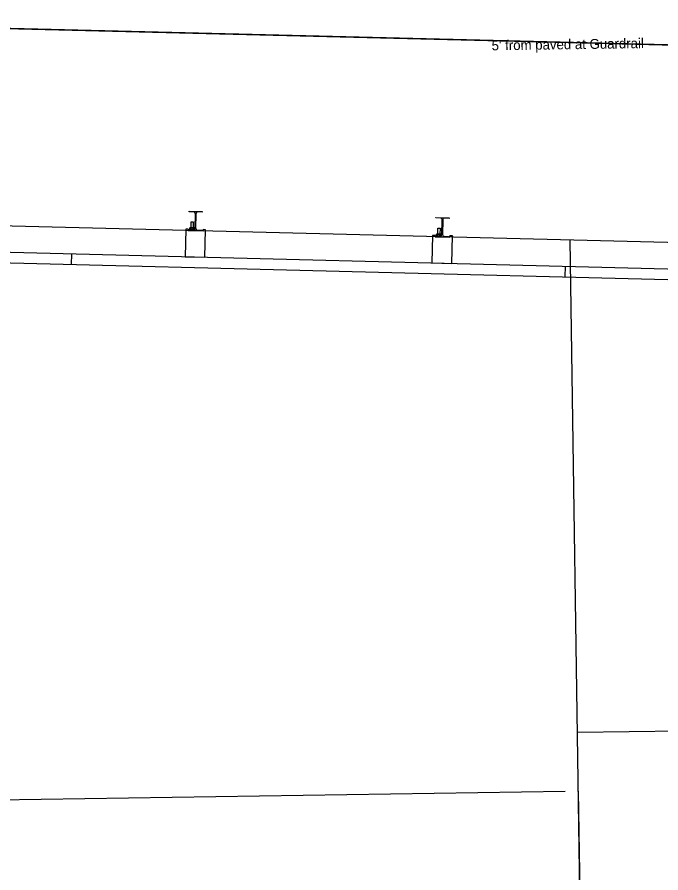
# Model space of a CAD drawing. Extents: x 17498307 to 17498862, y 7167523 to 7167641.
# Drawn here: x 17498396.78 to 17498413.08, y 7167588.49 to 7167610.15 of the extents above; entities that cross this region are included whole.
import ezdxf

# ---------------------------------------------------------------- set-up
doc = ezdxf.new("R2010")
doc.units = 0
for name, color, linetype in [('_CIVIL_CONSTRUCTION', 7, 'Continuous'), ('Draft_DNC', 7, 'Continuous'), ('dsnCellsHighwaySymbols', 7, 'Continuous'), ('Sawcut', 7, 'Continuous'), ('TextAlignmentSml', 7, 'Continuous'), ('TL_ForeSlopeBarnRoof', 7, 'Continuous')]:
    doc.layers.add(name, color=color, linetype=linetype)

msp = doc.modelspace()

# ---------------------------------------------------------------- linework, layer by layer
at = {"layer": '_CIVIL_CONSTRUCTION'}
for p, q in [((17498411.495, 7167556.438), (17498410.778, 7167604.508)), ((17498410.964, 7167592.047), (17498460.958, 7167592.793))]:
    msp.add_line(p, q, dxfattribs=at)
msp.add_lwpolyline([(17498432.532, 7167603.967), (17498384.798, 7167605.153)], dxfattribs=at)
at = {"layer": 'Draft_DNC'}
msp.add_line((17498432.656, 7167608.966), (17498384.922, 7167610.151), dxfattribs=at)
at = {"layer": 'dsnCellsHighwaySymbols'}
for p, q in [((17498401.134, 7167605.223), (17498401.134, 7167605.239)), ((17498401.134, 7167605.239), (17498401.467, 7167605.23)), ((17498401.134, 7167605.223), (17498401.134, 7167605.239)), ((17498401.134, 7167605.239), (17498401.467, 7167605.23)), ((17498401.251, 7167605.22), (17498401.134, 7167605.223)), ((17498401.251, 7167605.22), (17498401.134, 7167605.223)), ((17498401.282, 7167604.803), (17498401.292, 7167605.178)), ((17498401.282, 7167604.803), (17498401.292, 7167605.178)), ((17498401.307, 7167605.177), (17498401.298, 7167604.802)), ((17498401.307, 7167605.177), (17498401.298, 7167604.802)), ((17498401.467, 7167605.215), (17498401.35, 7167605.218)), ((17498401.467, 7167605.215), (17498401.35, 7167605.218)), ((17498401.467, 7167605.23), (17498401.467, 7167605.215)), ((17498401.467, 7167605.23), (17498401.467, 7167605.215)), ((17498401.181, 7167604.816), (17498401.185, 7167604.967)), ((17498401.185, 7167604.967), (17498401.237, 7167604.965)), ((17498401.237, 7167604.965), (17498401.233, 7167604.814)), ((17498407.382, 7167605.081), (17498407.715, 7167605.073)), ((17498407.382, 7167605.066), (17498407.382, 7167605.081)), ((17498407.499, 7167605.063), (17498407.382, 7167605.066)), ((17498407.53, 7167604.645), (17498407.54, 7167605.02)), ((17498407.555, 7167605.02), (17498407.546, 7167604.645)), ((17498407.715, 7167605.057), (17498407.598, 7167605.06)), ((17498407.715, 7167605.073), (17498407.715, 7167605.057)), ((17498401.05, 7167604.782), (17498401.032, 7167604.086)), ((17498401.112, 7167604.781), (17498401.05, 7167604.782)), ((17498401.112, 7167604.781), (17498401.111, 7167604.75)), ((17498401.111, 7167604.75), (17498401.486, 7167604.74)), ((17498401.122, 7167604.749), (17498401.122, 7167604.765)), ((17498401.122, 7167604.765), (17498401.239, 7167604.762)), ((17498401.122, 7167604.749), (17498401.122, 7167604.765)), ((17498401.122, 7167604.765), (17498401.239, 7167604.762)), ((17498401.455, 7167604.741), (17498401.122, 7167604.749)), ((17498401.455, 7167604.741), (17498401.122, 7167604.749)), ((17498401.146, 7167604.77), (17498401.147, 7167604.811)), ((17498401.146, 7167604.77), (17498401.147, 7167604.811)), ((17498401.154, 7167604.764), (17498401.146, 7167604.77)), ((17498401.154, 7167604.764), (17498401.146, 7167604.77)), ((17498401.147, 7167604.811), (17498401.155, 7167604.816)), ((17498401.162, 7167604.816), (17498401.155, 7167604.816)), ((17498401.259, 7167604.814), (17498401.162, 7167604.816)), ((17498401.176, 7167604.769), (17498401.177, 7167604.811)), ((17498401.177, 7167604.811), (17498401.176, 7167604.769)), ((17498401.176, 7167604.769), (17498401.177, 7167604.811)), ((17498401.237, 7167604.809), (17498401.236, 7167604.767)), ((17498401.236, 7167604.767), (17498401.237, 7167604.809)), ((17498401.236, 7167604.767), (17498401.237, 7167604.809)), ((17498401.259, 7167604.814), (17498401.267, 7167604.808)), ((17498401.267, 7167604.808), (17498401.266, 7167604.771)), ((17498401.266, 7167604.771), (17498401.267, 7167604.808)), ((17498401.338, 7167604.76), (17498401.455, 7167604.757)), ((17498401.338, 7167604.76), (17498401.455, 7167604.757)), ((17498401.455, 7167604.757), (17498401.455, 7167604.741)), ((17498401.455, 7167604.757), (17498401.455, 7167604.741)), ((17498401.486, 7167604.74), (17498401.487, 7167604.771)), ((17498401.55, 7167604.77), (17498401.487, 7167604.771)), ((17498401.532, 7167604.074), (17498401.55, 7167604.77)), ((17498407.429, 7167604.658), (17498407.433, 7167604.809)), ((17498407.433, 7167604.809), (17498407.485, 7167604.808)), ((17498407.485, 7167604.808), (17498407.481, 7167604.657)), ((17498407.298, 7167604.625), (17498407.28, 7167603.929)), ((17498407.36, 7167604.623), (17498407.298, 7167604.625)), ((17498407.36, 7167604.623), (17498407.359, 7167604.592)), ((17498407.359, 7167604.592), (17498407.734, 7167604.583)), ((17498407.37, 7167604.608), (17498407.487, 7167604.605)), ((17498407.37, 7167604.592), (17498407.37, 7167604.608)), ((17498407.703, 7167604.584), (17498407.37, 7167604.592)), ((17498407.394, 7167604.612), (17498407.395, 7167604.654)), ((17498407.394, 7167604.612), (17498407.395, 7167604.654)), ((17498407.402, 7167604.607), (17498407.394, 7167604.612)), ((17498407.402, 7167604.607), (17498407.394, 7167604.612)), ((17498407.395, 7167604.654), (17498407.403, 7167604.659)), ((17498407.41, 7167604.659), (17498407.403, 7167604.659)), ((17498407.507, 7167604.656), (17498407.41, 7167604.659)), ((17498407.424, 7167604.612), (17498407.425, 7167604.653)), ((17498407.425, 7167604.653), (17498407.424, 7167604.612)), ((17498407.424, 7167604.612), (17498407.425, 7167604.653)), ((17498407.485, 7167604.652), (17498407.484, 7167604.61)), ((17498407.484, 7167604.61), (17498407.485, 7167604.652)), ((17498407.484, 7167604.61), (17498407.485, 7167604.652)), ((17498407.487, 7167604.605), (17498407.487, 7167604.605)), ((17498407.487, 7167604.605), (17498407.487, 7167604.605)), ((17498407.507, 7167604.656), (17498407.515, 7167604.651)), ((17498407.515, 7167604.651), (17498407.514, 7167604.613)), ((17498407.514, 7167604.613), (17498407.515, 7167604.651)), ((17498407.586, 7167604.602), (17498407.703, 7167604.599)), ((17498407.703, 7167604.599), (17498407.703, 7167604.584)), ((17498407.734, 7167604.583), (17498407.735, 7167604.614)), ((17498407.798, 7167604.612), (17498407.735, 7167604.614)), ((17498407.78, 7167603.916), (17498407.798, 7167604.612)), ((17498407.28, 7167603.929), (17498407.78, 7167603.916))]:
    msp.add_line(p, q, dxfattribs=at)
for points in [[(17498401.181, 7167604.816), (17498401.185, 7167604.967), (17498401.237, 7167604.965), (17498401.233, 7167604.814)], [(17498407.429, 7167604.658), (17498407.433, 7167604.809), (17498407.485, 7167604.808), (17498407.481, 7167604.657)]]:
    msp.add_lwpolyline(points, close=True, dxfattribs=at)
for points in [[(17498401.147, 7167604.811), (17498401.155, 7167604.816), (17498401.162, 7167604.816), (17498401.259, 7167604.814), (17498401.267, 7167604.808)], [(17498401.239, 7167604.762), (17498401.154, 7167604.764), (17498401.154, 7167604.764)], [(17498401.266, 7167604.771), (17498401.266, 7167604.771)], [(17498407.395, 7167604.654), (17498407.403, 7167604.659), (17498407.41, 7167604.659), (17498407.507, 7167604.656), (17498407.515, 7167604.651)], [(17498407.487, 7167604.605), (17498407.402, 7167604.607), (17498407.402, 7167604.607)], [(17498407.514, 7167604.613), (17498407.514, 7167604.613)]]:
    msp.add_lwpolyline(points, dxfattribs=at)
for centre, start, end in [((17498401.25, 7167605.179), 358.5601, 88.5491), ((17498401.25, 7167605.179), 358.5601, 88.5491), ((17498401.349, 7167605.176), 88.5539, 178.5631), ((17498401.349, 7167605.176), 88.5539, 178.5631), ((17498407.498, 7167605.021), 358.5601, 88.5491), ((17498407.597, 7167605.019), 88.5539, 178.5631), ((17498401.24, 7167604.804), 268.5539, 358.5631), ((17498401.24, 7167604.804), 268.5539, 358.5631), ((17498401.24, 7167604.804), 268.5539, 307.6698), ((17498401.339, 7167604.801), 178.5601, 268.5491), ((17498401.339, 7167604.801), 178.5601, 268.5491), ((17498407.488, 7167604.646), 268.5539, 358.5631), ((17498407.488, 7167604.646), 268.5539, 307.6698), ((17498407.488, 7167604.646), 268.5539, 268.555), ((17498407.587, 7167604.644), 178.5601, 268.5491)]:
    msp.add_arc(centre, 0.0417, start, end, dxfattribs=at)
for points in [[(17498401.176, 7167604.769), (17498401.174, 7167604.768), (17498401.171, 7167604.766), (17498401.164, 7167604.764), (17498401.157, 7167604.764), (17498401.151, 7167604.767), (17498401.147, 7167604.769), (17498401.146, 7167604.77)], [(17498401.146, 7167604.77), (17498401.147, 7167604.769), (17498401.151, 7167604.767), (17498401.157, 7167604.764), (17498401.164, 7167604.764), (17498401.171, 7167604.766), (17498401.174, 7167604.768), (17498401.176, 7167604.769)], [(17498401.176, 7167604.769), (17498401.174, 7167604.768), (17498401.171, 7167604.766), (17498401.164, 7167604.764), (17498401.157, 7167604.764), (17498401.151, 7167604.767), (17498401.147, 7167604.769), (17498401.146, 7167604.77)], [(17498401.147, 7167604.811), (17498401.148, 7167604.812), (17498401.152, 7167604.814), (17498401.158, 7167604.816), (17498401.165, 7167604.816), (17498401.172, 7167604.814), (17498401.175, 7167604.811), (17498401.177, 7167604.811)], [(17498401.177, 7167604.811), (17498401.175, 7167604.811), (17498401.172, 7167604.814), (17498401.165, 7167604.816), (17498401.158, 7167604.816), (17498401.152, 7167604.814), (17498401.148, 7167604.812), (17498401.147, 7167604.811)], [(17498401.147, 7167604.811), (17498401.148, 7167604.812), (17498401.152, 7167604.814), (17498401.158, 7167604.816), (17498401.165, 7167604.816), (17498401.172, 7167604.814), (17498401.175, 7167604.811), (17498401.177, 7167604.811)], [(17498401.236, 7167604.767), (17498401.23, 7167604.766), (17498401.22, 7167604.763), (17498401.204, 7167604.763), (17498401.189, 7167604.765), (17498401.18, 7167604.768), (17498401.176, 7167604.769)], [(17498401.176, 7167604.769), (17498401.18, 7167604.768), (17498401.189, 7167604.765), (17498401.204, 7167604.763), (17498401.22, 7167604.763), (17498401.23, 7167604.766), (17498401.236, 7167604.767)], [(17498401.236, 7167604.767), (17498401.23, 7167604.766), (17498401.22, 7167604.763), (17498401.204, 7167604.763), (17498401.189, 7167604.765), (17498401.18, 7167604.768), (17498401.176, 7167604.769)], [(17498401.177, 7167604.811), (17498401.182, 7167604.812), (17498401.193, 7167604.815), (17498401.208, 7167604.815), (17498401.223, 7167604.813), (17498401.232, 7167604.81), (17498401.237, 7167604.809)], [(17498401.237, 7167604.809), (17498401.232, 7167604.81), (17498401.223, 7167604.813), (17498401.208, 7167604.815), (17498401.193, 7167604.815), (17498401.182, 7167604.812), (17498401.177, 7167604.811)], [(17498401.177, 7167604.811), (17498401.182, 7167604.812), (17498401.193, 7167604.815), (17498401.208, 7167604.815), (17498401.223, 7167604.813), (17498401.232, 7167604.81), (17498401.237, 7167604.809)], [(17498401.237, 7167604.809), (17498401.239, 7167604.81), (17498401.244, 7167604.813), (17498401.253, 7167604.814), (17498401.26, 7167604.812), (17498401.265, 7167604.81), (17498401.267, 7167604.808)], [(17498401.267, 7167604.808), (17498401.265, 7167604.81), (17498401.26, 7167604.812), (17498401.253, 7167604.814), (17498401.244, 7167604.813), (17498401.239, 7167604.81), (17498401.237, 7167604.809)], [(17498401.237, 7167604.809), (17498401.239, 7167604.81), (17498401.244, 7167604.813), (17498401.253, 7167604.814), (17498401.26, 7167604.812), (17498401.265, 7167604.81), (17498401.267, 7167604.808)], [(17498401.246, 7167604.763), (17498401.245, 7167604.763), (17498401.241, 7167604.764), (17498401.238, 7167604.766), (17498401.236, 7167604.767)], [(17498407.424, 7167604.612), (17498407.422, 7167604.611), (17498407.419, 7167604.609), (17498407.412, 7167604.607), (17498407.405, 7167604.607), (17498407.399, 7167604.609), (17498407.395, 7167604.611), (17498407.394, 7167604.612)], [(17498407.394, 7167604.612), (17498407.395, 7167604.611), (17498407.399, 7167604.609), (17498407.405, 7167604.607), (17498407.412, 7167604.607), (17498407.419, 7167604.609), (17498407.422, 7167604.611), (17498407.424, 7167604.612)], [(17498407.424, 7167604.612), (17498407.422, 7167604.611), (17498407.419, 7167604.609), (17498407.412, 7167604.607), (17498407.405, 7167604.607), (17498407.399, 7167604.609), (17498407.395, 7167604.611), (17498407.394, 7167604.612)], [(17498407.395, 7167604.654), (17498407.396, 7167604.655), (17498407.4, 7167604.657), (17498407.406, 7167604.659), (17498407.413, 7167604.659), (17498407.42, 7167604.656), (17498407.423, 7167604.654), (17498407.425, 7167604.653)], [(17498407.425, 7167604.653), (17498407.423, 7167604.654), (17498407.42, 7167604.656), (17498407.413, 7167604.659), (17498407.406, 7167604.659), (17498407.4, 7167604.657), (17498407.396, 7167604.655), (17498407.395, 7167604.654)], [(17498407.395, 7167604.654), (17498407.396, 7167604.655), (17498407.4, 7167604.657), (17498407.406, 7167604.659), (17498407.413, 7167604.659), (17498407.42, 7167604.656), (17498407.423, 7167604.654), (17498407.425, 7167604.653)], [(17498407.484, 7167604.61), (17498407.478, 7167604.609), (17498407.468, 7167604.606), (17498407.452, 7167604.605), (17498407.437, 7167604.607), (17498407.428, 7167604.61), (17498407.424, 7167604.612)], [(17498407.424, 7167604.612), (17498407.428, 7167604.61), (17498407.437, 7167604.607), (17498407.452, 7167604.605), (17498407.468, 7167604.606), (17498407.478, 7167604.609), (17498407.484, 7167604.61)], [(17498407.484, 7167604.61), (17498407.478, 7167604.609), (17498407.468, 7167604.606), (17498407.452, 7167604.605), (17498407.437, 7167604.607), (17498407.428, 7167604.61), (17498407.424, 7167604.612)], [(17498407.425, 7167604.653), (17498407.43, 7167604.654), (17498407.441, 7167604.657), (17498407.456, 7167604.658), (17498407.471, 7167604.656), (17498407.48, 7167604.653), (17498407.485, 7167604.652)], [(17498407.485, 7167604.652), (17498407.48, 7167604.653), (17498407.471, 7167604.656), (17498407.456, 7167604.658), (17498407.441, 7167604.657), (17498407.43, 7167604.654), (17498407.425, 7167604.653)], [(17498407.425, 7167604.653), (17498407.43, 7167604.654), (17498407.441, 7167604.657), (17498407.456, 7167604.658), (17498407.471, 7167604.656), (17498407.48, 7167604.653), (17498407.485, 7167604.652)], [(17498407.485, 7167604.652), (17498407.487, 7167604.653), (17498407.492, 7167604.656), (17498407.501, 7167604.657), (17498407.508, 7167604.655), (17498407.513, 7167604.652), (17498407.515, 7167604.651)], [(17498407.515, 7167604.651), (17498407.513, 7167604.652), (17498407.508, 7167604.655), (17498407.501, 7167604.657), (17498407.492, 7167604.656), (17498407.487, 7167604.653), (17498407.485, 7167604.652)], [(17498407.485, 7167604.652), (17498407.487, 7167604.653), (17498407.492, 7167604.656), (17498407.501, 7167604.657), (17498407.508, 7167604.655), (17498407.513, 7167604.652), (17498407.515, 7167604.651)], [(17498407.494, 7167604.606), (17498407.493, 7167604.606), (17498407.489, 7167604.607), (17498407.486, 7167604.609), (17498407.484, 7167604.61)]]:
    msp.add_open_spline(points, degree=3, dxfattribs=at)
at = {"layer": 'Sawcut'}
for p, q in [((17498365.03, 7167589.871), (17498410.656, 7167590.552)), ((17498410.986, 7167590.556), (17498411.299, 7167569.574))]:
    msp.add_line(p, q, dxfattribs=at)
at = {"layer": 'TextAlignmentSml'}
for p, q in [((17498401.134, 7167605.223), (17498401.134, 7167605.239)), ((17498401.134, 7167605.239), (17498401.467, 7167605.23)), ((17498401.251, 7167605.22), (17498401.134, 7167605.223)), ((17498401.282, 7167604.803), (17498401.292, 7167605.178)), ((17498401.307, 7167605.177), (17498401.298, 7167604.802)), ((17498401.467, 7167605.215), (17498401.35, 7167605.218)), ((17498401.467, 7167605.23), (17498401.467, 7167605.215)), ((17498401.181, 7167604.816), (17498401.185, 7167604.967)), ((17498401.185, 7167604.967), (17498401.237, 7167604.965)), ((17498401.237, 7167604.965), (17498401.233, 7167604.814)), ((17498407.382, 7167605.081), (17498407.715, 7167605.073)), ((17498407.382, 7167605.066), (17498407.382, 7167605.081)), ((17498407.499, 7167605.063), (17498407.382, 7167605.066)), ((17498407.53, 7167604.645), (17498407.54, 7167605.02)), ((17498407.555, 7167605.02), (17498407.546, 7167604.645)), ((17498407.715, 7167605.057), (17498407.598, 7167605.06)), ((17498407.715, 7167605.073), (17498407.715, 7167605.057)), ((17498401.05, 7167604.782), (17498401.032, 7167604.086)), ((17498401.112, 7167604.781), (17498401.05, 7167604.782)), ((17498401.112, 7167604.781), (17498401.111, 7167604.75)), ((17498401.111, 7167604.75), (17498401.486, 7167604.74)), ((17498401.122, 7167604.749), (17498401.122, 7167604.765)), ((17498401.122, 7167604.765), (17498401.239, 7167604.762)), ((17498401.455, 7167604.741), (17498401.122, 7167604.749)), ((17498401.146, 7167604.77), (17498401.147, 7167604.811)), ((17498401.154, 7167604.764), (17498401.146, 7167604.77)), ((17498401.147, 7167604.811), (17498401.155, 7167604.816)), ((17498401.162, 7167604.816), (17498401.155, 7167604.816)), ((17498401.259, 7167604.814), (17498401.162, 7167604.816)), ((17498401.176, 7167604.769), (17498401.177, 7167604.811)), ((17498401.236, 7167604.767), (17498401.237, 7167604.809)), ((17498401.259, 7167604.814), (17498401.267, 7167604.808)), ((17498401.266, 7167604.771), (17498401.267, 7167604.808)), ((17498401.338, 7167604.76), (17498401.455, 7167604.757)), ((17498401.455, 7167604.757), (17498401.455, 7167604.741)), ((17498401.486, 7167604.74), (17498401.487, 7167604.771)), ((17498401.55, 7167604.77), (17498401.487, 7167604.771)), ((17498401.532, 7167604.074), (17498401.55, 7167604.77)), ((17498407.429, 7167604.658), (17498407.433, 7167604.809)), ((17498407.433, 7167604.809), (17498407.485, 7167604.808)), ((17498407.485, 7167604.808), (17498407.481, 7167604.657)), ((17498407.298, 7167604.625), (17498407.28, 7167603.929)), ((17498407.36, 7167604.623), (17498407.298, 7167604.625)), ((17498407.36, 7167604.623), (17498407.359, 7167604.592)), ((17498407.359, 7167604.592), (17498407.734, 7167604.583)), ((17498407.37, 7167604.608), (17498407.487, 7167604.605)), ((17498407.37, 7167604.592), (17498407.37, 7167604.608)), ((17498407.703, 7167604.584), (17498407.37, 7167604.592)), ((17498407.394, 7167604.612), (17498407.395, 7167604.654)), ((17498407.402, 7167604.607), (17498407.394, 7167604.612)), ((17498407.395, 7167604.654), (17498407.403, 7167604.659)), ((17498407.41, 7167604.659), (17498407.403, 7167604.659)), ((17498407.507, 7167604.656), (17498407.41, 7167604.659)), ((17498407.424, 7167604.612), (17498407.425, 7167604.653)), ((17498407.484, 7167604.61), (17498407.485, 7167604.652)), ((17498407.507, 7167604.656), (17498407.515, 7167604.651)), ((17498407.514, 7167604.613), (17498407.515, 7167604.651)), ((17498407.586, 7167604.602), (17498407.703, 7167604.599)), ((17498407.703, 7167604.599), (17498407.703, 7167604.584)), ((17498407.734, 7167604.583), (17498407.735, 7167604.614)), ((17498407.798, 7167604.612), (17498407.735, 7167604.614)), ((17498407.78, 7167603.916), (17498407.798, 7167604.612)), ((17498394.462, 7167604.252), (17498435.649, 7167603.214)), ((17498398.158, 7167604.159), (17498398.151, 7167603.888)), ((17498401.032, 7167604.086), (17498401.532, 7167604.074)), ((17498394.455, 7167603.981), (17498435.642, 7167602.944)), ((17498407.28, 7167603.929), (17498407.78, 7167603.916)), ((17498410.654, 7167603.844), (17498410.647, 7167603.573))]:
    msp.add_line(p, q, dxfattribs=at)
for centre, start, end in [((17498401.25, 7167605.179), 358.5601, 88.5491), ((17498401.349, 7167605.176), 88.5539, 178.5631), ((17498407.498, 7167605.021), 358.5601, 88.5491), ((17498407.597, 7167605.019), 88.5539, 178.5631), ((17498401.24, 7167604.804), 268.5539, 358.5631), ((17498401.339, 7167604.801), 178.5601, 268.5491), ((17498407.488, 7167604.646), 268.5539, 358.5631), ((17498407.587, 7167604.644), 178.5601, 268.5491)]:
    msp.add_arc(centre, 0.0417, start, end, dxfattribs=at)
for points in [[(17498401.176, 7167604.769), (17498401.174, 7167604.768), (17498401.171, 7167604.766), (17498401.164, 7167604.764), (17498401.157, 7167604.764), (17498401.151, 7167604.767), (17498401.147, 7167604.769), (17498401.146, 7167604.77)], [(17498401.147, 7167604.811), (17498401.148, 7167604.812), (17498401.152, 7167604.814), (17498401.158, 7167604.816), (17498401.165, 7167604.816), (17498401.172, 7167604.814), (17498401.175, 7167604.811), (17498401.177, 7167604.811)], [(17498401.236, 7167604.767), (17498401.23, 7167604.766), (17498401.22, 7167604.763), (17498401.204, 7167604.763), (17498401.189, 7167604.765), (17498401.18, 7167604.768), (17498401.176, 7167604.769)], [(17498401.177, 7167604.811), (17498401.182, 7167604.812), (17498401.193, 7167604.815), (17498401.208, 7167604.815), (17498401.223, 7167604.813), (17498401.232, 7167604.81), (17498401.237, 7167604.809)], [(17498401.237, 7167604.809), (17498401.239, 7167604.81), (17498401.244, 7167604.813), (17498401.253, 7167604.814), (17498401.26, 7167604.812), (17498401.265, 7167604.81), (17498401.267, 7167604.808)], [(17498401.246, 7167604.763), (17498401.245, 7167604.763), (17498401.241, 7167604.764), (17498401.238, 7167604.766), (17498401.236, 7167604.767)], [(17498407.424, 7167604.612), (17498407.422, 7167604.611), (17498407.419, 7167604.609), (17498407.412, 7167604.607), (17498407.405, 7167604.607), (17498407.399, 7167604.609), (17498407.395, 7167604.611), (17498407.394, 7167604.612)], [(17498407.395, 7167604.654), (17498407.396, 7167604.655), (17498407.4, 7167604.657), (17498407.406, 7167604.659), (17498407.413, 7167604.659), (17498407.42, 7167604.656), (17498407.423, 7167604.654), (17498407.425, 7167604.653)], [(17498407.484, 7167604.61), (17498407.478, 7167604.609), (17498407.468, 7167604.606), (17498407.452, 7167604.605), (17498407.437, 7167604.607), (17498407.428, 7167604.61), (17498407.424, 7167604.612)], [(17498407.425, 7167604.653), (17498407.43, 7167604.654), (17498407.441, 7167604.657), (17498407.456, 7167604.658), (17498407.471, 7167604.656), (17498407.48, 7167604.653), (17498407.485, 7167604.652)], [(17498407.485, 7167604.652), (17498407.487, 7167604.653), (17498407.492, 7167604.656), (17498407.501, 7167604.657), (17498407.508, 7167604.655), (17498407.513, 7167604.652), (17498407.515, 7167604.651)], [(17498407.494, 7167604.606), (17498407.493, 7167604.606), (17498407.489, 7167604.607), (17498407.486, 7167604.609), (17498407.484, 7167604.61)]]:
    msp.add_open_spline(points, degree=3, dxfattribs=at)
at = {"layer": 'TL_ForeSlopeBarnRoof'}
msp.add_lwpolyline([(17498364.726, 7167609.85), (17498384.922, 7167610.151), (17498432.461, 7167608.967), (17498440.339, 7167609.079), (17498491.727, 7167609.807)], dxfattribs=at)

# ---------------------------------------------------------------- texts
at = {"layer": 'Draft_DNC'}
msp.add_text("5' from paved at Guardrail", height=0.25, rotation=0.8552, dxfattribs=at).set_placement((17498408.793, 7167609.309))

doc.saveas('drawing.dxf')
